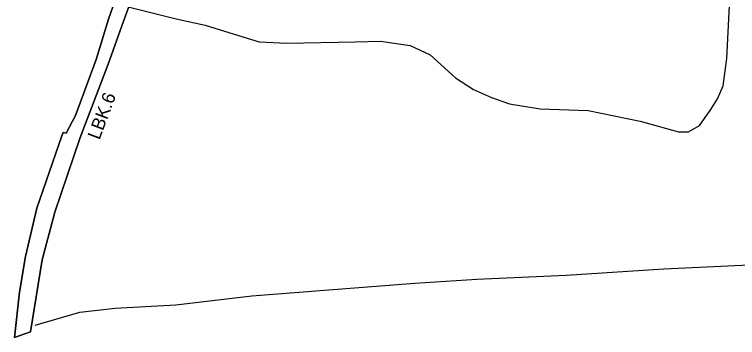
# Model space of a CAD drawing. Extents: x -555426 to -553015, y -1186745 to -1182595.
# Drawn here: x -555426 to -554710, y -1186725 to -1186406 of the extents above; entities that cross this region are included whole.
import ezdxf

# ---------------------------------------------------------------- set-up
doc = ezdxf.new("R2010")
doc.units = 0
for name, color, linetype in [('Level 12', 7, 'Continuous'), ('Level 51', 7, 'Continuous'), ('svahove_deformace', 7, 'Continuous'), ('USES_ID', 7, 'Continuous'), ('USES_LBK_navrh', 7, 'Continuous')]:
    doc.layers.add(name, color=color, linetype=linetype)

msp = doc.modelspace()

# ---------------------------------------------------------------- linework, layer by layer
at = {"layer": 'Level 12'}
for points in [[(-555298.22, -1186307.56), (-555310.66, -1186348.84), (-555332.46, -1186411.11), (-555344.77, -1186450.74), (-555365.28, -1186506.04), (-555374.35, -1186523.58), (-555377.44, -1186522.92), (-555378.76, -1186526.22), (-555403.3, -1186597.68), (-555414.63, -1186645.4), (-555420.53, -1186680.78), (-555425.54, -1186725.43), (-555420.84, -1186723.67)], [(-555420.84, -1186723.67), (-555415.22, -1186721.67), (-555409.6, -1186719.66), (-555398.08, -1186648.64), (-555385.52, -1186601.65), (-555360.47, -1186527.99), (-555332.87, -1186455.38), (-555317.95, -1186413.97), (-555281.22, -1186313.35)]]:
    msp.add_lwpolyline(points, dxfattribs=at)
at = {"layer": 'Level 51'}
msp.add_lwpolyline([(-555405.09, -1186713.35), (-555360.97, -1186700.42), (-555326.09, -1186696.49), (-555265.8, -1186693.26), (-555190.72, -1186684.25), (-555123.27, -1186678.93), (-555029.48, -1186671.77), (-554968.32, -1186667.73), (-554879.85, -1186663.92), (-554783.35, -1186657.45), (-554698.8, -1186653.52)], dxfattribs=at)
at = {"layer": 'svahove_deformace'}
msp.add_lwpolyline([(-555311.67, -1186398.97), (-555265.71, -1186410.61), (-555236.92, -1186416.74), (-555203.83, -1186427.16), (-555183.61, -1186433.28), (-555156.04, -1186434.51), (-555088.64, -1186433.28), (-555063.52, -1186432.67), (-555034.11, -1186436.96), (-555014.5, -1186446.15), (-554989.38, -1186468.82), (-554971.61, -1186480.46), (-554953.84, -1186488.43), (-554936.07, -1186494.56), (-554905.44, -1186499.46), (-554858.26, -1186501.3), (-554806.79, -1186511.71), (-554768.8, -1186522.13), (-554759, -1186522.13), (-554747.97, -1186516), (-554737.56, -1186501.3), (-554730.2, -1186489.65), (-554724.69, -1186476.79), (-554721.01, -1186449.83), (-554717.95, -1186390.39)], dxfattribs=at)
at = {"layer": 'USES_LBK_navrh'}
for p, q in [((-555281.22, -1186313.35), (-555317.95, -1186413.97)), ((-555317.95, -1186413.97), (-555332.87, -1186455.38)), ((-555332.87, -1186455.38), (-555360.47, -1186527.99)), ((-555403.3, -1186597.68), (-555378.76, -1186526.22)), ((-555360.47, -1186527.99), (-555385.52, -1186601.65)), ((-555414.63, -1186645.4), (-555403.3, -1186597.68)), ((-555385.52, -1186601.65), (-555398.08, -1186648.64)), ((-555398.08, -1186648.64), (-555409.6, -1186719.66))]:
    msp.add_line(p, q, dxfattribs=at)
for points in [[(-555374.35, -1186523.58), (-555365.28, -1186506.04), (-555344.77, -1186450.74), (-555332.46, -1186411.11), (-555310.66, -1186348.84), (-555298.22, -1186307.56)], [(-555378.76, -1186526.22), (-555377.44, -1186522.92), (-555374.35, -1186523.58)], [(-555420.84, -1186723.67), (-555425.54, -1186725.43), (-555420.53, -1186680.78), (-555414.63, -1186645.4)], [(-555409.6, -1186719.66), (-555415.22, -1186721.67), (-555420.84, -1186723.67)]]:
    msp.add_lwpolyline(points, dxfattribs=at)

# ---------------------------------------------------------------- texts
at = {"layer": 'USES_ID'}
msp.add_text('LBK.6', height=13, rotation=69.42323, dxfattribs=at).set_placement((-555341.51, -1186530.82))

doc.saveas('drawing.dxf')
